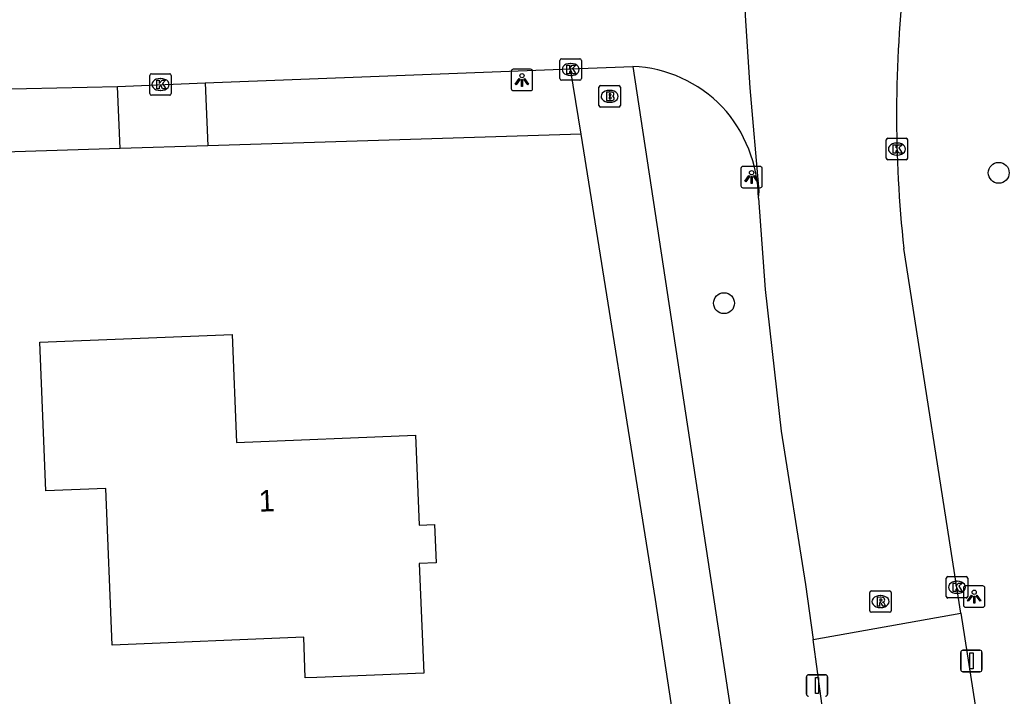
# Model space of a CAD drawing. Extents: x 162417 to 163721, y 384268 to 385416.
# Drawn here: x 163231.73 to 163277.95, y 385159.48 to 385191.06 of the extents above; entities that cross this region are included whole.
import ezdxf

# ---------------------------------------------------------------- set-up
doc = ezdxf.new("R2010")
doc.units = 0
for name, color, linetype in [('IMGEO_Afsluitpaal', 7, 'Continuous'), ('IMGEO_Berm_groen', 7, 'Continuous'), ('IMGEO_Boom', 7, 'Continuous'), ('IMGEO_Brandkraan', 7, 'Continuous'), ('IMGEO_Grasland_overig', 7, 'Continuous'), ('IMGEO_Kolk', 7, 'Continuous'), ('IMGEO_Lichtpunt', 7, 'Continuous'), ('IMGEO_Pand', 7, 'Continuous'), ('IMGEO_Pand_nummerreeks', 7, 'Continuous'), ('IMGEO_Rijbaan_lokaal_gesloten', 7, 'Continuous'), ('IMGEO_Rijbaan_lokaal_open', 7, 'Continuous'), ('IMGEO_Rioolput', 7, 'Continuous'), ('IMGEO_Voetpad_open', 7, 'Continuous')]:
    doc.layers.add(name, color=color, linetype=linetype)

msp = doc.modelspace()

# ---------------------------------------------------------------- linework, layer by layer
at = {"layer": 'IMGEO_Afsluitpaal'}
for p, q in [((163275.789, 385161.622), (163276.579, 385161.622)), ((163276.579, 385161.622), (163275.789, 385161.622)), ((163275.689, 385160.722), (163275.689, 385161.522)), ((163275.689, 385161.522), (163275.689, 385160.722)), ((163276.679, 385161.522), (163276.679, 385160.722)), ((163276.679, 385160.722), (163276.679, 385161.522)), ((163268.477, 385159.576), (163268.477, 385160.376)), ((163268.477, 385160.376), (163268.477, 385159.576)), ((163268.577, 385160.476), (163269.367, 385160.476)), ((163269.367, 385160.476), (163268.577, 385160.476)), ((163269.467, 385160.376), (163269.467, 385159.576)), ((163269.467, 385159.576), (163269.467, 385160.376)), ((163276.579, 385160.622), (163275.789, 385160.622)), ((163275.789, 385160.622), (163276.579, 385160.622))]:
    msp.add_line(p, q, dxfattribs=at)
for points in [[(163276.109, 385161.497), (163276.259, 385161.497), (163276.259, 385160.747), (163276.109, 385160.747), (163276.109, 385161.497)], [(163268.897, 385160.351), (163269.047, 385160.351), (163269.047, 385159.601), (163268.897, 385159.601), (163268.897, 385160.351)]]:
    msp.add_lwpolyline(points, dxfattribs=at)
for centre, start, end in [((163275.789, 385161.522), 90, 180), ((163275.789, 385161.522), 90, 180), ((163276.579, 385161.522), 0, 90), ((163276.579, 385161.522), 360, 90), ((163275.789, 385160.722), 180, 270), ((163275.789, 385160.722), 180, 270), ((163276.579, 385160.722), 270, 0), ((163276.579, 385160.722), 270, 0), ((163268.577, 385160.376), 90, 180), ((163268.577, 385160.376), 90, 180), ((163269.367, 385160.376), 0, 90), ((163269.367, 385160.376), 360, 90), ((163268.577, 385159.576), 180, 270), ((163268.577, 385159.576), 180, 270), ((163269.367, 385159.576), 270, 0), ((163269.367, 385159.576), 270, 0)]:
    msp.add_arc(centre, 0.1, start, end, dxfattribs=at)
at = {"layer": 'IMGEO_Berm_groen'}
msp.add_lwpolyline([(163257.947, 385185.727), (163240.507, 385185.177)], dxfattribs=at)
at = {"layer": 'IMGEO_Boom'}
for centre in [(163277.461, 385183.919), (163264.626, 385177.83)]:
    msp.add_circle(centre, 0.489, dxfattribs=at)
at = {"layer": 'IMGEO_Brandkraan'}
for p, q in [((163258.783, 385187.064), (163258.783, 385187.916)), ((163258.858, 385187.99), (163259.71, 385187.99)), ((163259.784, 385187.916), (163259.784, 385187.064)), ((163259.271, 385187.77), (163259.296, 385187.77)), ((163259.71, 385186.99), (163258.858, 385186.99)), ((163259.294, 385187.21), (163259.269, 385187.21))]:
    msp.add_line(p, q, dxfattribs=at)
for points in [[(163258.783, 385187.064), (163258.783, 385187.916)], [(163258.858, 385187.99), (163259.71, 385187.99)], [(163259.784, 385187.916), (163259.784, 385187.064)], [(163259.131, 385187.69), (163259.131, 385187.29), (163259.344, 385187.29)], [(163259.362, 385187.69), (163259.131, 385187.69)], [(163259.31, 385187.609), (163259.256, 385187.609), (163259.256, 385187.533)], [(163259.256, 385187.533), (163259.309, 385187.533)], [(163259.318, 385187.457), (163259.256, 385187.457), (163259.256, 385187.376)], [(163259.71, 385186.99), (163258.858, 385186.99)], [(163259.256, 385187.376), (163259.318, 385187.376)]]:
    msp.add_lwpolyline(points, dxfattribs=at)
for centre, radius, start, end in [((163258.86, 385187.914), 0.0765, 91.552, 178.448), ((163258.86, 385187.914), 0.0765, 91.552, 178.448), ((163259.708, 385187.914), 0.0765, 1.552, 88.448), ((163259.708, 385187.914), 0.0765, 1.552, 88.448), ((163259.311, 385187.571), 0.0379, 267.8285, 90.9355), ((163259.319, 385187.416), 0.0404, 269.8759, 90.5077), ((163259.366, 385187.545), 0.145, 59.4692, 91.5367), ((163259.391, 385187.592), 0.0922, 285.5137, 58.1501), ((163259.396, 385187.4), 0.105, 301.3115, 78.989), ((163258.86, 385187.066), 0.0765, 181.552, 268.448), ((163258.86, 385187.066), 0.0765, 181.552, 268.448), ((163259.35, 385187.541), 0.251, 268.6676, 293.5347), ((163259.708, 385187.066), 0.0765, 271.552, 358.448), ((163259.708, 385187.066), 0.0765, 271.552, 358.448)]:
    msp.add_arc(centre, radius, start, end, dxfattribs=at)
for centre, major_axis, ratio, start_param, end_param in [((163259.27, 385187.49), (-0.387, 0.002), 0.722429, 4.712389, 7.853982), ((163259.295, 385187.49), (-0.39, 0.002), 0.717154, 1.570796, 4.712389)]:
    msp.add_ellipse(centre, major_axis=major_axis, ratio=ratio, start_param=start_param, end_param=end_param, dxfattribs=at)
at = {"layer": 'IMGEO_Grasland_overig'}
msp.add_lwpolyline([(163236.412, 385185.048), (163223.611, 385184.644), (163223.52, 385187.664)], dxfattribs=at)
at = {"layer": 'IMGEO_Kolk'}
for p, q in [((163256.963, 385188.319), (163256.963, 385189.171)), ((163257.038, 385189.245), (163257.89, 385189.245)), ((163257.451, 385189.025), (163257.476, 385189.025)), ((163257.964, 385189.171), (163257.964, 385188.319)), ((163237.803, 385187.616), (163237.803, 385188.468)), ((163237.878, 385188.542), (163238.73, 385188.542)), ((163238.804, 385188.468), (163238.804, 385187.616)), ((163257.474, 385188.465), (163257.449, 385188.465)), ((163238.291, 385188.322), (163238.316, 385188.322)), ((163257.89, 385188.245), (163257.038, 385188.245)), ((163238.73, 385187.542), (163237.878, 385187.542)), ((163238.314, 385187.762), (163238.289, 385187.762)), ((163272.205, 385184.603), (163272.205, 385185.455)), ((163272.28, 385185.529), (163273.132, 385185.529)), ((163272.693, 385185.309), (163272.718, 385185.309)), ((163273.206, 385185.455), (163273.206, 385184.603)), ((163272.716, 385184.749), (163272.691, 385184.749)), ((163273.132, 385184.529), (163272.28, 385184.529)), ((163275.011, 385164.137), (163275.011, 385164.989)), ((163275.086, 385165.063), (163275.938, 385165.063)), ((163275.499, 385164.843), (163275.524, 385164.843)), ((163276.012, 385164.989), (163276.012, 385164.137)), ((163275.938, 385164.063), (163275.086, 385164.063)), ((163275.522, 385164.283), (163275.497, 385164.283))]:
    msp.add_line(p, q, dxfattribs=at)
for points in [[(163256.963, 385188.319), (163256.963, 385189.171)], [(163257.038, 385189.245), (163257.89, 385189.245)], [(163257.284, 385188.945), (163257.407, 385188.945), (163257.407, 385188.794), (163257.537, 385188.945), (163257.701, 385188.945), (163257.555, 385188.794), (163257.708, 385188.545), (163257.556, 385188.545), (163257.471, 385188.709), (163257.407, 385188.642), (163257.407, 385188.545), (163257.284, 385188.545), (163257.284, 385188.945)], [(163257.964, 385189.171), (163257.964, 385188.319)], [(163237.803, 385187.616), (163237.803, 385188.468)], [(163237.878, 385188.542), (163238.73, 385188.542)], [(163238.804, 385188.468), (163238.804, 385187.616)], [(163238.124, 385188.242), (163238.247, 385188.242), (163238.247, 385188.091), (163238.377, 385188.242), (163238.541, 385188.242), (163238.395, 385188.091), (163238.548, 385187.842), (163238.396, 385187.842), (163238.311, 385188.006), (163238.247, 385187.939), (163238.247, 385187.842), (163238.124, 385187.842), (163238.124, 385188.242)], [(163257.89, 385188.245), (163257.038, 385188.245)], [(163238.73, 385187.542), (163237.878, 385187.542)], [(163272.205, 385184.603), (163272.205, 385185.455)], [(163272.28, 385185.529), (163273.132, 385185.529)], [(163272.526, 385185.229), (163272.649, 385185.229), (163272.649, 385185.078), (163272.779, 385185.229), (163272.943, 385185.229), (163272.797, 385185.078), (163272.95, 385184.829), (163272.798, 385184.829), (163272.713, 385184.993), (163272.649, 385184.926), (163272.649, 385184.829), (163272.526, 385184.829), (163272.526, 385185.229)], [(163273.206, 385185.455), (163273.206, 385184.603)], [(163273.132, 385184.529), (163272.28, 385184.529)], [(163275.011, 385164.137), (163275.011, 385164.989)], [(163275.086, 385165.063), (163275.938, 385165.063)], [(163276.012, 385164.989), (163276.012, 385164.137)], [(163275.332, 385164.763), (163275.455, 385164.763), (163275.455, 385164.612), (163275.585, 385164.763), (163275.749, 385164.763), (163275.603, 385164.612), (163275.756, 385164.363), (163275.604, 385164.363), (163275.519, 385164.527), (163275.455, 385164.46), (163275.455, 385164.363), (163275.332, 385164.363), (163275.332, 385164.763)], [(163275.938, 385164.063), (163275.086, 385164.063)]]:
    msp.add_lwpolyline(points, dxfattribs=at)
for centre, start, end in [((163257.04, 385189.169), 91.552, 178.448), ((163257.04, 385189.169), 91.552, 178.448), ((163257.888, 385189.169), 1.552, 88.448), ((163257.888, 385189.169), 1.552, 88.448), ((163237.88, 385188.466), 91.552, 178.448), ((163237.88, 385188.466), 91.552, 178.448), ((163238.728, 385188.466), 1.552, 88.448), ((163238.728, 385188.466), 1.552, 88.448), ((163257.04, 385188.321), 181.552, 268.448), ((163257.04, 385188.321), 181.552, 268.448), ((163257.888, 385188.321), 271.552, 358.448), ((163257.888, 385188.321), 271.552, 358.448), ((163237.88, 385187.618), 181.552, 268.448), ((163237.88, 385187.618), 181.552, 268.448), ((163238.728, 385187.618), 271.552, 358.448), ((163238.728, 385187.618), 271.552, 358.448), ((163272.282, 385185.453), 91.552, 178.448), ((163272.282, 385185.453), 91.552, 178.448), ((163273.13, 385185.453), 1.552, 88.448), ((163273.13, 385185.453), 1.552, 88.448), ((163272.282, 385184.605), 181.552, 268.448), ((163272.282, 385184.605), 181.552, 268.448), ((163273.13, 385184.605), 271.552, 358.448), ((163273.13, 385184.605), 271.552, 358.448), ((163275.088, 385164.987), 91.552, 178.448), ((163275.088, 385164.987), 91.552, 178.448), ((163275.936, 385164.987), 1.552, 88.448), ((163275.936, 385164.987), 1.552, 88.448), ((163275.088, 385164.139), 181.552, 268.448), ((163275.088, 385164.139), 181.552, 268.448), ((163275.936, 385164.139), 271.552, 358.448), ((163275.936, 385164.139), 271.552, 358.448)]:
    msp.add_arc(centre, 0.0765, start, end, dxfattribs=at)
for centre, major_axis, ratio, start_param, end_param in [((163257.45, 385188.745), (-0.387, 0.002), 0.722429, 4.712389, 7.853982), ((163257.475, 385188.745), (-0.39, 0.002), 0.717154, 1.570796, 4.712389), ((163238.29, 385188.042), (-0.387, 0.002), 0.722429, 4.712389, 7.853982), ((163238.315, 385188.042), (-0.39, 0.002), 0.717154, 1.570796, 4.712389), ((163272.692, 385185.029), (-0.387, 0.002), 0.722429, 4.712389, 7.853982), ((163272.717, 385185.029), (-0.39, 0.002), 0.717154, 1.570796, 4.712389), ((163275.498, 385164.563), (-0.387, 0.002), 0.722429, 4.712389, 7.853982), ((163275.523, 385164.563), (-0.39, 0.002), 0.717154, 1.570796, 4.712389)]:
    msp.add_ellipse(centre, major_axis=major_axis, ratio=ratio, start_param=start_param, end_param=end_param, dxfattribs=at)
at = {"layer": 'IMGEO_Lichtpunt'}
for p, q in [((163254.689, 385188.657), (163254.689, 385187.85)), ((163254.689, 385188.657), (163254.689, 385187.85)), ((163255.591, 385188.752), (163254.783, 385188.752)), ((163255.591, 385188.752), (163254.783, 385188.752)), ((163255.685, 385187.85), (163255.685, 385188.657)), ((163255.685, 385187.85), (163255.685, 385188.657)), ((163254.783, 385187.756), (163255.591, 385187.756)), ((163254.783, 385187.756), (163255.591, 385187.756)), ((163266.316, 385184.218), (163265.508, 385184.218)), ((163266.316, 385184.218), (163265.508, 385184.218)), ((163265.414, 385184.123), (163265.414, 385183.316)), ((163265.414, 385184.123), (163265.414, 385183.316)), ((163266.41, 385183.316), (163266.41, 385184.123)), ((163266.41, 385183.316), (163266.41, 385184.123)), ((163265.508, 385183.222), (163266.316, 385183.222)), ((163265.508, 385183.222), (163266.316, 385183.222)), ((163275.815, 385164.534), (163275.815, 385163.727)), ((163275.815, 385164.534), (163275.815, 385163.727)), ((163276.717, 385164.629), (163275.909, 385164.629)), ((163276.717, 385164.629), (163275.909, 385164.629)), ((163276.811, 385163.727), (163276.811, 385164.534)), ((163276.811, 385163.727), (163276.811, 385164.534)), ((163275.909, 385163.633), (163276.717, 385163.633)), ((163275.909, 385163.633), (163276.717, 385163.633))]:
    msp.add_line(p, q, dxfattribs=at)
for points in [[(163255.063, 385188.321), (163255.102, 385188.293), (163254.914, 385188.031), (163254.876, 385188.058), (163255.063, 385188.321)], [(163255.165, 385188.273), (163255.212, 385188.273), (163255.212, 385187.951), (163255.165, 385187.951), (163255.165, 385188.273)], [(163255.275, 385188.293), (163255.313, 385188.32), (163255.5, 385188.058), (163255.461, 385188.03), (163255.275, 385188.293)], [(163265.788, 385183.787), (163265.827, 385183.759), (163265.639, 385183.497), (163265.601, 385183.524), (163265.788, 385183.787)], [(163266, 385183.759), (163266.038, 385183.786), (163266.225, 385183.524), (163266.186, 385183.496), (163266, 385183.759)], [(163265.89, 385183.739), (163265.937, 385183.739), (163265.937, 385183.417), (163265.89, 385183.417), (163265.89, 385183.739)], [(163276.189, 385164.198), (163276.228, 385164.17), (163276.04, 385163.908), (163276.002, 385163.935), (163276.189, 385164.198)], [(163276.291, 385164.15), (163276.338, 385164.15), (163276.338, 385163.828), (163276.291, 385163.828), (163276.291, 385164.15)], [(163276.401, 385164.17), (163276.439, 385164.197), (163276.626, 385163.935), (163276.587, 385163.907), (163276.401, 385164.17)]]:
    msp.add_lwpolyline(points, dxfattribs=at)
for centre in [(163255.188, 385188.455), (163265.913, 385183.921), (163276.314, 385164.332)]:
    msp.add_circle(centre, 0.0994, dxfattribs=at)
for centre, start, end in [((163254.783, 385188.657), 90, 180), ((163254.783, 385188.657), 90, 180), ((163255.591, 385188.657), 0, 90), ((163255.591, 385188.657), 0, 90), ((163254.783, 385187.85), 180, 270), ((163254.783, 385187.85), 180, 270), ((163255.591, 385187.85), 270, 0), ((163255.591, 385187.85), 270, 360), ((163265.508, 385184.123), 90, 180), ((163265.508, 385184.123), 90, 180), ((163266.316, 385184.123), 0, 90), ((163266.316, 385184.123), 0, 90), ((163265.508, 385183.316), 180, 270), ((163265.508, 385183.316), 180, 270), ((163266.316, 385183.316), 270, 0), ((163266.316, 385183.316), 270, 360), ((163275.909, 385164.534), 90, 180), ((163275.909, 385164.534), 90, 180), ((163276.717, 385164.534), 0, 90), ((163276.717, 385164.534), 0, 90), ((163275.909, 385163.727), 180, 270), ((163275.909, 385163.727), 180, 270), ((163276.717, 385163.727), 270, 0), ((163276.717, 385163.727), 270, 360)]:
    msp.add_arc(centre, 0.0946, start, end, dxfattribs=at)
at = {"layer": 'IMGEO_Pand'}
msp.add_lwpolyline([(163232.87, 385171.01), (163232.667, 385176.005), (163241.649, 385176.37), (163241.854, 385171.33), (163250.209, 385171.669), (163250.38, 385167.465), (163251.104, 385167.494), (163251.177, 385165.7), (163250.39, 385165.668), (163250.598, 385160.558), (163245.603, 385160.355), (163245.067, 385160.333), (163244.99, 385162.228), (163236.037, 385161.864), (163235.74, 385169.179), (163232.949, 385169.066), (163232.87, 385171.01)], dxfattribs=at)
at = {"layer": 'IMGEO_Rijbaan_lokaal_gesloten'}
for points in [[(163266.237, 385182.736), (163266.268, 385183.054), (163265.843, 385187.892), (163265.634, 385191.26), (163265.819, 385195.029), (163266.521, 385198.944)], [(163257.459, 385188.774), (163260.372, 385188.89)], [(163240.394, 385188.115), (163257.459, 385188.774)], [(163223.52, 385187.664), (163236.3, 385187.957)], [(163236.3, 385187.957), (163240.394, 385188.115)], [(163266.237, 385182.736), (163266.557, 385178.462), (163267.291, 385171.846), (163268.44, 385164.697), (163268.793, 385162.119)], [(163275.685, 385163.351), (163273.029, 385180.384)]]:
    msp.add_lwpolyline(points, dxfattribs=at)
for centre, radius, start, end in [((163329.631, 385186.646), 56.947, 173.3139, 186.3128), ((163260.073, 385182.676), 6.221, 44.0172, 87.248), ((163259.762, 385182.635), 6.476, 0.8896, 42.3605)]:
    msp.add_arc(centre, radius, start, end, dxfattribs=at)
at = {"layer": 'IMGEO_Rijbaan_lokaal_open'}
for points in [[(163268.793, 385162.119), (163275.685, 385163.351)], [(163275.685, 385163.351), (163276.433, 385158.553)], [(163269.477, 385157.482), (163269.201, 385159.139), (163268.793, 385162.119)]]:
    msp.add_lwpolyline(points, dxfattribs=at)
at = {"layer": 'IMGEO_Rioolput'}
for p, q in [((163271.513, 385164.395), (163272.365, 385164.395)), ((163271.438, 385163.469), (163271.438, 385164.321)), ((163271.926, 385164.175), (163271.951, 385164.175)), ((163272.439, 385164.321), (163272.439, 385163.469)), ((163271.949, 385163.615), (163271.924, 385163.615)), ((163272.365, 385163.395), (163271.513, 385163.395))]:
    msp.add_line(p, q, dxfattribs=at)
for points in [[(163271.513, 385164.395), (163272.365, 385164.395)], [(163271.438, 385163.469), (163271.438, 385164.321)], [(163272.027, 385164.093), (163271.775, 385164.095), (163271.775, 385163.695)], [(163271.953, 385164.014), (163271.899, 385164.014), (163271.899, 385163.933)], [(163271.899, 385163.933), (163271.951, 385163.933)], [(163272.439, 385164.321), (163272.439, 385163.469)], [(163271.775, 385163.695), (163271.899, 385163.695), (163271.899, 385163.857), (163271.91, 385163.857)], [(163271.957, 385163.828), (163272.028, 385163.695), (163272.168, 385163.695), (163272.103, 385163.821)], [(163272.365, 385163.395), (163271.513, 385163.395)]]:
    msp.add_lwpolyline(points, dxfattribs=at)
for centre, radius, start, end in [((163271.515, 385164.319), 0.0765, 91.552, 178.448), ((163271.515, 385164.319), 0.0765, 91.552, 178.448), ((163272.363, 385164.319), 0.0765, 1.552, 88.448), ((163272.363, 385164.319), 0.0765, 1.552, 88.448), ((163271.935, 385164.122), 0.19, 274.7715, 282.9687), ((163271.959, 385163.918), 0.0964, 77.0061, 93.1865), ((163271.973, 385163.975), 0.0378, 276.6634, 79.6772), ((163272.026, 385163.983), 0.109, 350.3612, 89.416), ((163272.024, 385163.983), 0.112, 277.5842, 350.9817), ((163271.515, 385163.471), 0.0765, 181.552, 268.448), ((163271.515, 385163.471), 0.0765, 181.552, 268.448), ((163271.909, 385163.804), 0.0533, 26.0293, 88.6989), ((163272.008, 385163.768), 0.108, 29.5134, 73.7905), ((163272.363, 385163.471), 0.0765, 271.552, 358.448), ((163272.363, 385163.471), 0.0765, 271.552, 358.448)]:
    msp.add_arc(centre, radius, start, end, dxfattribs=at)
for centre, major_axis, ratio, start_param, end_param in [((163271.925, 385163.895), (-0.387, 0.002), 0.722429, 4.712389, 7.853982), ((163271.95, 385163.895), (-0.39, 0.002), 0.717154, 1.570796, 4.712389)]:
    msp.add_ellipse(centre, major_axis=major_axis, ratio=ratio, start_param=start_param, end_param=end_param, dxfattribs=at)
at = {"layer": 'IMGEO_Voetpad_open'}
for points in [[(163260.372, 385188.89), (163268.602, 385134.675)], [(163257.947, 385185.727), (163257.459, 385188.774)], [(163236.412, 385185.048), (163236.3, 385187.957)], [(163240.394, 385188.115), (163240.507, 385185.177)], [(163265.986, 385133.92), (163261.426, 385163.999), (163257.947, 385185.727)], [(163240.507, 385185.177), (163236.412, 385185.048)]]:
    msp.add_lwpolyline(points, dxfattribs=at)

# ---------------------------------------------------------------- texts
at = {"layer": 'IMGEO_Pand_nummerreeks'}
msp.add_text('1', height=1, rotation=2.3235, dxfattribs=at).set_placement((163242.908, 385168.09))

doc.saveas('drawing.dxf')
